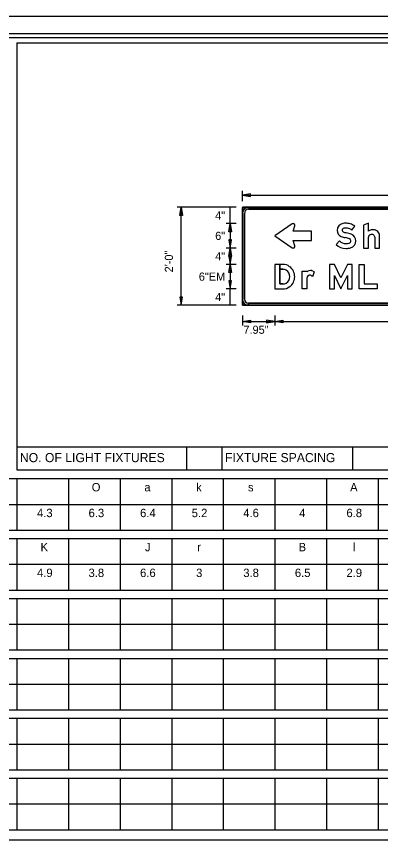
# Model space of a CAD drawing. Extents: x 1374 to 1480, y 568 to 638.
# Drawn here: x 1410.25 to 1417.68, y 587.74 to 604.64 of the extents above; entities that cross this region are included whole.
import ezdxf

# ---------------------------------------------------------------- set-up
doc = ezdxf.new("R2010")
doc.units = 0
for name, color, linetype in [('GSBWFill', 7, 'Continuous'), ('GSColorFill', 7, 'Continuous'), ('GSDims', 7, 'Continuous'), ('GSOutline', 7, 'Continuous'), ('GSSign', 7, 'Continuous'), ('PlotBorder_dp', 7, 'Continuous'), ('SheetBorder_dp', 7, 'Continuous'), ('SheetLinesMisc2_dp', 7, 'Continuous'), ('TextMinor', 7, 'Continuous')]:
    doc.layers.add(name, color=color, linetype=linetype)

msp = doc.modelspace()

# ---------------------------------------------------------------- linework, layer by layer
at = {"layer": 'GSBWFill'}
for p, q in [((1423.858, 600.75), (1414.858, 600.75)), ((1414.858, 600.75), (1414.858, 598.75)), ((1423.733, 600.75), (1414.983, 600.75)), ((1414.983, 600.708), (1423.733, 600.708)), ((1414.858, 600.625), (1414.858, 598.875)), ((1414.9, 598.875), (1414.9, 600.625)), ((1416.326, 599.432), (1416.292, 599.33)), ((1415.684, 599.183), (1415.62, 599.183)), ((1414.858, 598.75), (1423.858, 598.75)), ((1414.983, 598.75), (1414.983, 598.791)), ((1423.733, 598.791), (1414.984, 598.791)), ((1414.984, 598.791), (1414.984, 598.75)), ((1414.984, 598.75), (1423.733, 598.75))]:
    msp.add_line(p, q, dxfattribs=at)
for points in [[(1415.877, 600.41), (1415.521, 600.166), (1415.877, 599.923)], [(1416.271, 600.073), (1416.271, 600.259), (1415.897, 600.259), (1415.931, 600.37)], [(1417.091, 600.284), (1417.152, 600.363)], [(1417.431, 600.263), (1417.431, 600.425), (1417.331, 600.386), (1417.331, 599.916), (1417.431, 599.916), (1417.431, 600.136)], [(1417.561, 600.136), (1417.561, 599.916), (1417.661, 599.916), (1417.661, 600.168)], [(1415.931, 599.963), (1415.897, 600.073), (1416.271, 600.073)], [(1416.841, 600.063), (1416.771, 599.992)], [(1415.62, 599.183), (1415.62, 599.583), (1415.521, 599.583), (1415.521, 599.083), (1415.684, 599.083)], [(1415.684, 599.583), (1415.62, 599.583), (1415.62, 599.483), (1415.684, 599.483)], [(1416.176, 599.285), (1416.176, 599.083), (1416.076, 599.083), (1416.076, 599.448), (1416.176, 599.448), (1416.176, 599.432)]]:
    msp.add_lwpolyline(points, dxfattribs=at)
for points in [[(1417.003, 599.355), (1417.003, 599.083), (1417.103, 599.083), (1417.103, 599.583), (1417.003, 599.583), (1416.871, 599.311), (1416.738, 599.583), (1416.638, 599.583), (1416.638, 599.083), (1416.738, 599.083), (1416.738, 599.355), (1416.871, 599.083)], [(1417.343, 599.183), (1417.613, 599.183), (1417.613, 599.083), (1417.243, 599.083), (1417.243, 599.583), (1417.343, 599.583)]]:
    msp.add_lwpolyline(points, close=True, dxfattribs=at)
for centre, radius, start, end in [((1414.983, 600.625), 0.125, 90, 180), ((1414.983, 600.625), 0.0833, 90, 180), ((1415.897, 600.38), 0.0361, 342.9427, 124.3997), ((1416.938, 600.278), 0.143, 101.6172, 180), ((1416.968, 600.13), 0.295, 90, 101.6172), ((1416.968, 600.063), 0.361, 75.2778, 90), ((1417.002, 600.19), 0.229, 48.8597, 75.2778), ((1416.927, 600.278), 0.133, 180, 248.2079), ((1416.938, 600.278), 0.0432, 101.6172, 180), ((1416.927, 600.278), 0.0327, 180, 248.2079), ((1417.036, 600.55), 0.326, 248.2079, 259.4488), ((1416.968, 600.13), 0.195, 90, 101.6172), ((1416.968, 600.063), 0.261, 75.2778, 90), ((1416.865, 599.631), 0.609, 69.1129, 79.4488), ((1417.002, 600.19), 0.129, 46.4926, 75.2778), ((1417.03, 600.064), 0.146, 0, 69.1129), ((1417.527, 600.111), 0.18, 103.4695, 122.4943), ((1417.491, 600.132), 0.0609, 131.0076, 154.5283), ((1417.496, 600.126), 0.0688, 109.8074, 131.0076), ((1417.499, 600.116), 0.0787, 90, 109.8074), ((1417.529, 600.091), 0.2, 90, 102.6043), ((1417.499, 600.132), 0.0632, 68.0808, 90), ((1417.5, 600.134), 0.0613, 45.8298, 68.0808), ((1417.529, 600.15), 0.141, 68.8636, 90), ((1417.501, 600.135), 0.0598, 23.0928, 45.8298), ((1417.532, 600.159), 0.131, 46.975, 68.8636), ((1417.538, 600.165), 0.124, 23.9317, 46.975), ((1417.546, 600.168), 0.115, 0, 23.9317), ((1416.974, 600.198), 0.189, 225.2528, 270), ((1417.036, 600.55), 0.426, 248.2079, 259.4488), ((1416.865, 599.631), 0.509, 69.1129, 79.4488), ((1416.974, 600.263), 0.254, 270, 284.8926), ((1417.027, 600.064), 0.0485, 284.8926, 360), ((1417.03, 600.064), 0.0457, 360, 69.1129), ((1417.027, 600.064), 0.149, 284.8926, 360), ((1417.483, 600.136), 0.0521, 154.5283, 180), ((1417.503, 600.136), 0.058, 0, 23.0928), ((1415.897, 599.952), 0.0361, 235.6003, 17.0573), ((1416.974, 600.198), 0.289, 225.2528, 270), ((1416.974, 600.263), 0.354, 270, 284.8926), ((1414.983, 598.875), 0.125, 180, 270), ((1414.983, 598.875), 0.0833, 180, 270)]:
    msp.add_arc(centre, radius, start, end, dxfattribs=at)
for centre, major_axis, ratio, start_param, end_param in [((1415.69, 599.364), (0, 0.219), 0.992009, 5.621793, 6.313477), ((1415.679, 599.335), (0, 0.249), 0.992009, 4.702399, 5.655315), ((1415.686, 599.348), (0, 0.135), 0.992009, 5.75224, 6.301036), ((1415.677, 599.337), (0, 0.149), 0.992009, 4.686283, 5.735161), ((1415.677, 599.329), (0, 0.149), 0.992009, 3.689617, 4.738495), ((1415.679, 599.33), (0, 0.249), 0.992009, 3.769463, 4.722379), ((1416.276, 599.298), (0, 0.167), 0.99999, 0.443663, 0.646229), ((1416.255, 599.301), (0, 0.0781), 0.99999, 1.188904, 1.450084), ((1416.229, 599.312), (0, 0.05), 0.99999, 0.293855, 1.188904), ((1416.237, 599.381), (0, 0.075), 0.99999, 0.24142, 0.443663), ((1416.23, 599.309), (0, 0.0534), 0.99999, 0.067293, 0.293855), ((1416.25, 599.329), (0, 0.129), 0.99999, 6.103268, 6.524606), ((1416.231, 599.282), (0, 0.08), 0.99999, 6.094384, 6.350479), ((1416.234, 599.293), (0, 0.0688), 0.99999, 5.27661, 6.094384), ((1416.252, 599.345), (0, 0.112), 0.99999, 5.846069, 6.103268), ((1416.241, 599.321), (0, 0.14), 0.99999, 5.631644, 5.846069), ((1415.686, 599.318), (0, 0.135), 0.992009, 3.123742, 3.672538), ((1416.388, 599.284), (0, 0.212), 0.99999, 1.445958, 1.569673), ((1415.69, 599.302), (0, 0.219), 0.992009, 3.111301, 3.802985)]:
    msp.add_ellipse(centre, major_axis=major_axis, ratio=ratio, start_param=start_param, end_param=end_param, dxfattribs=at)
at = {"layer": 'GSColorFill'}
for p, q in [((1423.858, 600.75), (1414.858, 600.75)), ((1414.858, 600.75), (1414.858, 598.75)), ((1423.858, 600.75), (1414.858, 600.75)), ((1414.858, 600.75), (1414.858, 598.754)), ((1414.862, 598.754), (1414.862, 600.745)), ((1414.862, 600.745), (1423.854, 600.745)), ((1423.733, 600.75), (1414.983, 600.75)), ((1414.983, 600.708), (1423.733, 600.708)), ((1414.858, 600.625), (1414.858, 598.875)), ((1414.9, 598.875), (1414.9, 600.625)), ((1416.326, 599.432), (1416.292, 599.33)), ((1415.684, 599.183), (1415.62, 599.183)), ((1414.858, 598.754), (1414.862, 598.754)), ((1423.854, 598.754), (1414.858, 598.754)), ((1414.858, 598.754), (1414.858, 598.75)), ((1414.858, 598.75), (1423.858, 598.75)), ((1414.858, 598.75), (1423.858, 598.75)), ((1414.983, 598.75), (1414.983, 598.791)), ((1423.733, 598.791), (1414.984, 598.791)), ((1414.984, 598.791), (1414.984, 598.75)), ((1414.984, 598.75), (1423.733, 598.75))]:
    msp.add_line(p, q, dxfattribs=at)
for points in [[(1415.877, 600.41), (1415.521, 600.166), (1415.877, 599.923)], [(1416.271, 600.073), (1416.271, 600.259), (1415.897, 600.259), (1415.931, 600.37)], [(1417.091, 600.284), (1417.152, 600.363)], [(1417.431, 600.263), (1417.431, 600.425), (1417.331, 600.386), (1417.331, 599.916), (1417.431, 599.916), (1417.431, 600.136)], [(1417.561, 600.136), (1417.561, 599.916), (1417.661, 599.916), (1417.661, 600.168)], [(1415.931, 599.963), (1415.897, 600.073), (1416.271, 600.073)], [(1416.841, 600.063), (1416.771, 599.992)], [(1415.62, 599.183), (1415.62, 599.583), (1415.521, 599.583), (1415.521, 599.083), (1415.684, 599.083)], [(1415.684, 599.583), (1415.62, 599.583), (1415.62, 599.483), (1415.684, 599.483)], [(1416.176, 599.285), (1416.176, 599.083), (1416.076, 599.083), (1416.076, 599.448), (1416.176, 599.448), (1416.176, 599.432)]]:
    msp.add_lwpolyline(points, dxfattribs=at)
for points in [[(1417.003, 599.355), (1417.003, 599.083), (1417.103, 599.083), (1417.103, 599.583), (1417.003, 599.583), (1416.871, 599.311), (1416.738, 599.583), (1416.638, 599.583), (1416.638, 599.083), (1416.738, 599.083), (1416.738, 599.355), (1416.871, 599.083)], [(1417.343, 599.183), (1417.613, 599.183), (1417.613, 599.083), (1417.243, 599.083), (1417.243, 599.583), (1417.343, 599.583)]]:
    msp.add_lwpolyline(points, close=True, dxfattribs=at)
for centre, radius, start, end in [((1414.983, 600.625), 0.125, 90, 180), ((1414.983, 600.625), 0.0833, 90, 180), ((1415.897, 600.38), 0.0361, 342.9427, 124.3997), ((1416.938, 600.278), 0.143, 101.6172, 180), ((1416.968, 600.13), 0.295, 90, 101.6172), ((1416.968, 600.063), 0.361, 75.2778, 90), ((1417.002, 600.19), 0.229, 48.8597, 75.2778), ((1416.927, 600.278), 0.133, 180, 248.2079), ((1416.938, 600.278), 0.0432, 101.6172, 180), ((1416.927, 600.278), 0.0327, 180, 248.2079), ((1417.036, 600.55), 0.326, 248.2079, 259.4488), ((1416.968, 600.13), 0.195, 90, 101.6172), ((1416.968, 600.063), 0.261, 75.2778, 90), ((1416.865, 599.631), 0.609, 69.1129, 79.4488), ((1417.002, 600.19), 0.129, 46.4926, 75.2778), ((1417.03, 600.064), 0.146, 0, 69.1129), ((1417.527, 600.111), 0.18, 103.4695, 122.4943), ((1417.491, 600.132), 0.0609, 131.0076, 154.5283), ((1417.496, 600.126), 0.0688, 109.8074, 131.0076), ((1417.499, 600.116), 0.0787, 90, 109.8074), ((1417.529, 600.091), 0.2, 90, 102.6043), ((1417.499, 600.132), 0.0632, 68.0808, 90), ((1417.5, 600.134), 0.0613, 45.8298, 68.0808), ((1417.529, 600.15), 0.141, 68.8636, 90), ((1417.501, 600.135), 0.0598, 23.0928, 45.8298), ((1417.532, 600.159), 0.131, 46.975, 68.8636), ((1417.538, 600.165), 0.124, 23.9317, 46.975), ((1417.546, 600.168), 0.115, 0, 23.9317), ((1416.974, 600.198), 0.189, 225.2528, 270), ((1417.036, 600.55), 0.426, 248.2079, 259.4488), ((1416.865, 599.631), 0.509, 69.1129, 79.4488), ((1416.974, 600.263), 0.254, 270, 284.8926), ((1417.027, 600.064), 0.0485, 284.8926, 360), ((1417.03, 600.064), 0.0457, 360, 69.1129), ((1417.027, 600.064), 0.149, 284.8926, 360), ((1417.483, 600.136), 0.0521, 154.5283, 180), ((1417.503, 600.136), 0.058, 0, 23.0928), ((1415.897, 599.952), 0.0361, 235.6003, 17.0573), ((1416.974, 600.198), 0.289, 225.2528, 270), ((1416.974, 600.263), 0.354, 270, 284.8926), ((1414.983, 598.875), 0.125, 180, 270), ((1414.983, 598.875), 0.0833, 180, 270)]:
    msp.add_arc(centre, radius, start, end, dxfattribs=at)
for centre, major_axis, ratio, start_param, end_param in [((1415.69, 599.364), (0, 0.219), 0.992009, 5.621793, 6.313477), ((1415.679, 599.335), (0, 0.249), 0.992009, 4.702399, 5.655315), ((1415.686, 599.348), (0, 0.135), 0.992009, 5.75224, 6.301036), ((1415.677, 599.337), (0, 0.149), 0.992009, 4.686283, 5.735161), ((1415.677, 599.329), (0, 0.149), 0.992009, 3.689617, 4.738495), ((1415.679, 599.33), (0, 0.249), 0.992009, 3.769463, 4.722379), ((1416.276, 599.298), (0, 0.167), 0.99999, 0.443663, 0.646229), ((1416.255, 599.301), (0, 0.0781), 0.99999, 1.188904, 1.450084), ((1416.229, 599.312), (0, 0.05), 0.99999, 0.293855, 1.188904), ((1416.237, 599.381), (0, 0.075), 0.99999, 0.24142, 0.443663), ((1416.23, 599.309), (0, 0.0534), 0.99999, 0.067293, 0.293855), ((1416.25, 599.329), (0, 0.129), 0.99999, 6.103268, 6.524606), ((1416.231, 599.282), (0, 0.08), 0.99999, 6.094384, 6.350479), ((1416.234, 599.293), (0, 0.0688), 0.99999, 5.27661, 6.094384), ((1416.252, 599.345), (0, 0.112), 0.99999, 5.846069, 6.103268), ((1416.241, 599.321), (0, 0.14), 0.99999, 5.631644, 5.846069), ((1415.686, 599.318), (0, 0.135), 0.992009, 3.123742, 3.672538), ((1416.388, 599.284), (0, 0.212), 0.99999, 1.445958, 1.569673), ((1415.69, 599.302), (0, 0.219), 0.992009, 3.111301, 3.802985)]:
    msp.add_ellipse(centre, major_axis=major_axis, ratio=ratio, start_param=start_param, end_param=end_param, dxfattribs=at)
at = {"layer": 'GSDims'}
for p, q in [((1414.858, 600.875), (1414.858, 601.083)), ((1414.858, 601), (1423.858, 601)), ((1414.858, 600.875), (1414.858, 600.875)), ((1413.733, 600.75), (1413.525, 600.75)), ((1413.608, 598.75), (1413.608, 600.75)), ((1414.733, 600.75), (1413.733, 600.75)), ((1414.733, 600.75), (1414.525, 600.75)), ((1414.608, 600.416), (1414.608, 600.75)), ((1414.733, 600.416), (1414.525, 600.416)), ((1414.733, 600.416), (1414.525, 600.416)), ((1414.608, 600.416), (1414.608, 599.916)), ((1414.733, 599.916), (1414.525, 599.916)), ((1414.733, 599.916), (1414.525, 599.916)), ((1414.608, 599.583), (1414.608, 599.916)), ((1414.733, 599.583), (1414.525, 599.583)), ((1414.733, 599.583), (1414.525, 599.583)), ((1414.608, 599.583), (1414.608, 599.083)), ((1414.733, 599.083), (1414.525, 599.083)), ((1414.733, 599.083), (1414.525, 599.083)), ((1414.608, 598.75), (1414.608, 599.083)), ((1413.733, 598.75), (1413.525, 598.75)), ((1414.733, 598.75), (1413.733, 598.75)), ((1414.733, 598.75), (1414.525, 598.75)), ((1414.858, 598.541), (1414.858, 598.333)), ((1414.858, 598.541), (1414.858, 598.333)), ((1415.521, 598.541), (1415.521, 598.333)), ((1415.521, 598.541), (1415.521, 598.333)), ((1414.858, 598.416), (1415.521, 598.416)), ((1415.521, 598.416), (1423.196, 598.416))]:
    msp.add_line(p, q, dxfattribs=at)
for points in [[(1414.858, 601), (1415.025, 600.972), (1415.025, 601.027)], [(1413.608, 600.75), (1413.636, 600.583), (1413.58, 600.583)], [(1414.608, 600.416), (1414.636, 600.25), (1414.58, 600.25)], [(1414.608, 599.916), (1414.636, 600.083), (1414.58, 600.083)], [(1414.608, 599.916), (1414.636, 599.75), (1414.58, 599.75)], [(1414.608, 599.583), (1414.636, 599.75), (1414.58, 599.75)], [(1414.608, 599.583), (1414.636, 599.416), (1414.58, 599.416)], [(1414.608, 599.083), (1414.636, 599.25), (1414.58, 599.25)], [(1413.608, 598.75), (1413.636, 598.916), (1413.58, 598.916)], [(1414.858, 598.416), (1415.025, 598.444), (1415.025, 598.388)], [(1415.521, 598.416), (1415.354, 598.444), (1415.354, 598.388)], [(1415.521, 598.416), (1415.687, 598.444), (1415.687, 598.388)]]:
    msp.add_lwpolyline(points, close=True, dxfattribs=at)
at = {"layer": 'GSOutline'}
for p, q in [((1423.858, 600.75), (1414.858, 600.75)), ((1414.858, 600.75), (1414.858, 598.75)), ((1423.733, 600.75), (1414.983, 600.75)), ((1423.733, 600.708), (1414.983, 600.708)), ((1414.858, 600.625), (1414.858, 598.875)), ((1414.9, 600.625), (1414.9, 598.875)), ((1416.326, 599.432), (1416.292, 599.33)), ((1415.684, 599.183), (1415.684, 599.183)), ((1415.684, 599.083), (1415.684, 599.083)), ((1414.858, 598.75), (1423.858, 598.75)), ((1414.983, 598.791), (1423.733, 598.791)), ((1414.983, 598.75), (1423.733, 598.75))]:
    msp.add_line(p, q, dxfattribs=at)
for points in [[(1415.877, 600.41), (1415.521, 600.166), (1415.877, 599.923)], [(1416.271, 600.073), (1416.271, 600.259), (1415.897, 600.259), (1415.931, 600.37)], [(1417.091, 600.284), (1417.152, 600.363)], [(1417.431, 600.263), (1417.431, 600.425), (1417.331, 600.386), (1417.331, 599.916), (1417.431, 599.916), (1417.431, 600.136)], [(1417.561, 600.136), (1417.561, 599.916), (1417.661, 599.916), (1417.661, 600.168)], [(1415.931, 599.963), (1415.897, 600.073), (1416.271, 600.073)], [(1416.841, 600.063), (1416.771, 599.992)], [(1415.684, 599.583), (1415.521, 599.583), (1415.521, 599.083), (1415.684, 599.083)], [(1415.684, 599.483), (1415.62, 599.483), (1415.62, 599.183), (1415.684, 599.183)], [(1416.176, 599.285), (1416.176, 599.083), (1416.076, 599.083), (1416.076, 599.448), (1416.176, 599.448), (1416.176, 599.432)]]:
    msp.add_lwpolyline(points, dxfattribs=at)
for points in [[(1417.003, 599.355), (1417.003, 599.083), (1417.103, 599.083), (1417.103, 599.583), (1417.003, 599.583), (1416.871, 599.311), (1416.738, 599.583), (1416.638, 599.583), (1416.638, 599.083), (1416.738, 599.083), (1416.738, 599.355), (1416.871, 599.083)], [(1417.343, 599.183), (1417.613, 599.183), (1417.613, 599.083), (1417.243, 599.083), (1417.243, 599.583), (1417.343, 599.583)]]:
    msp.add_lwpolyline(points, close=True, dxfattribs=at)
for centre, radius, start, end in [((1414.983, 600.625), 0.125, 90, 180), ((1414.983, 600.625), 0.0833, 90, 180), ((1415.897, 600.38), 0.0361, 342.9427, 124.3997), ((1416.938, 600.278), 0.143, 101.6172, 180), ((1416.968, 600.13), 0.295, 90, 101.6172), ((1416.968, 600.063), 0.361, 75.2778, 90), ((1417.002, 600.19), 0.229, 48.8597, 75.2778), ((1416.927, 600.278), 0.133, 180, 248.2079), ((1416.938, 600.278), 0.0432, 101.6172, 180), ((1416.927, 600.278), 0.0327, 180, 248.2079), ((1417.036, 600.55), 0.326, 248.2079, 259.4488), ((1416.968, 600.13), 0.195, 90, 101.6172), ((1416.968, 600.063), 0.261, 75.2778, 90), ((1416.865, 599.631), 0.609, 69.1129, 79.4488), ((1417.002, 600.19), 0.129, 46.4926, 75.2778), ((1417.03, 600.064), 0.146, 0, 69.1129), ((1417.527, 600.111), 0.18, 103.4695, 122.4943), ((1417.491, 600.132), 0.0609, 131.0076, 154.5283), ((1417.496, 600.126), 0.0688, 109.8074, 131.0076), ((1417.499, 600.116), 0.0787, 90, 109.8074), ((1417.529, 600.091), 0.2, 90, 102.6043), ((1417.499, 600.132), 0.0632, 68.0808, 90), ((1417.5, 600.134), 0.0613, 45.8298, 68.0808), ((1417.529, 600.15), 0.141, 68.8636, 90), ((1417.501, 600.135), 0.0598, 23.0928, 45.8298), ((1417.532, 600.159), 0.131, 46.975, 68.8636), ((1417.538, 600.165), 0.124, 23.9317, 46.975), ((1417.546, 600.168), 0.115, 0, 23.9317), ((1416.974, 600.198), 0.189, 225.2528, 270), ((1417.036, 600.55), 0.426, 248.2079, 259.4488), ((1416.865, 599.631), 0.509, 69.1129, 79.4488), ((1416.974, 600.263), 0.254, 270, 284.8926), ((1417.027, 600.064), 0.0485, 284.8926, 360), ((1417.03, 600.064), 0.0457, 360, 69.1129), ((1417.027, 600.064), 0.149, 284.8926, 360), ((1417.483, 600.136), 0.0521, 154.5283, 180), ((1417.503, 600.136), 0.058, 0, 23.0928), ((1415.897, 599.952), 0.0361, 235.6003, 17.0573), ((1416.974, 600.198), 0.289, 225.2528, 270), ((1416.974, 600.263), 0.354, 270, 284.8926), ((1414.983, 598.875), 0.125, 180, 270), ((1414.983, 598.875), 0.0833, 180, 270)]:
    msp.add_arc(centre, radius, start, end, dxfattribs=at)
for centre, major_axis, ratio, start_param, end_param in [((1415.69, 599.364), (0, 0.219), 0.992009, 5.621793, 6.313477), ((1415.679, 599.335), (0, 0.249), 0.992009, 4.702399, 5.655315), ((1415.686, 599.348), (0, 0.135), 0.992009, 5.75224, 6.301036), ((1415.677, 599.337), (0, 0.149), 0.992009, 4.686283, 5.735161), ((1415.677, 599.329), (0, 0.149), 0.992009, 3.689617, 4.738495), ((1415.679, 599.33), (0, 0.249), 0.992009, 3.769463, 4.722379), ((1416.276, 599.298), (0, 0.167), 0.99999, 0.443663, 0.646229), ((1416.255, 599.301), (0, 0.0781), 0.99999, 1.188904, 1.450084), ((1416.229, 599.312), (0, 0.05), 0.99999, 0.293855, 1.188904), ((1416.237, 599.381), (0, 0.075), 0.99999, 0.24142, 0.443663), ((1416.23, 599.309), (0, 0.0534), 0.99999, 0.067293, 0.293855), ((1416.25, 599.329), (0, 0.129), 0.99999, 6.103268, 6.524606), ((1416.231, 599.282), (0, 0.08), 0.99999, 6.094384, 6.350479), ((1416.234, 599.293), (0, 0.0688), 0.99999, 5.27661, 6.094384), ((1416.252, 599.345), (0, 0.113), 0.99999, 5.846069, 6.103268), ((1416.241, 599.321), (0, 0.14), 0.99999, 5.631644, 5.846069), ((1415.686, 599.318), (0, 0.135), 0.992009, 3.123742, 3.672538), ((1416.388, 599.284), (0, 0.212), 0.99999, 1.445958, 1.569673), ((1415.69, 599.302), (0, 0.219), 0.992009, 3.111301, 3.802985)]:
    msp.add_ellipse(centre, major_axis=major_axis, ratio=ratio, start_param=start_param, end_param=end_param, dxfattribs=at)
at = {"layer": 'PlotBorder_dp'}
msp.add_lwpolyline([(1400.035, 568.275), (1456.648, 568.275), (1456.648, 604.644), (1400.035, 604.644)], close=True, dxfattribs=at)
at = {"layer": 'SheetBorder_dp'}
msp.add_line((1401.922, 604.301), (1454.76, 604.301), dxfattribs=at)
at = {"layer": 'SheetLinesMisc2_dp'}
for p, q in [((1402.016, 604.22), (1454.669, 604.22)), ((1410.256, 604.111), (1428.163, 604.111)), ((1410.256, 604.111), (1410.256, 595.388)), ((1410.256, 595.855), (1428.163, 595.855)), ((1413.715, 595.855), (1413.715, 595.388)), ((1414.439, 595.855), (1414.439, 595.388)), ((1417.106, 595.855), (1417.106, 595.388)), ((1410.256, 595.388), (1428.163, 595.388)), ((1402.268, 595.208), (1428.163, 595.208)), ((1410.256, 595.208), (1410.256, 594.156)), ((1411.309, 595.208), (1411.309, 594.156)), ((1412.362, 595.208), (1412.362, 594.156)), ((1413.415, 595.208), (1413.415, 594.156)), ((1414.469, 595.208), (1414.469, 594.156)), ((1415.522, 595.208), (1415.522, 594.156)), ((1416.576, 595.208), (1416.576, 594.156)), ((1417.629, 595.208), (1417.629, 594.156)), ((1402.268, 594.682), (1428.163, 594.682)), ((1402.268, 594.156), (1428.163, 594.156)), ((1402.268, 593.985), (1428.163, 593.985)), ((1410.256, 593.985), (1410.256, 592.933)), ((1411.309, 593.985), (1411.309, 592.933)), ((1412.362, 593.985), (1412.362, 592.933)), ((1413.415, 593.985), (1413.415, 592.933)), ((1414.469, 593.985), (1414.469, 592.933)), ((1415.522, 593.985), (1415.522, 592.933)), ((1416.576, 593.985), (1416.576, 592.933)), ((1417.629, 593.985), (1417.629, 592.933)), ((1402.268, 593.459), (1428.163, 593.459)), ((1402.268, 592.933), (1428.163, 592.933)), ((1402.268, 592.761), (1428.163, 592.761)), ((1410.256, 592.761), (1410.256, 591.709)), ((1411.309, 592.761), (1411.309, 591.709)), ((1412.362, 592.761), (1412.362, 591.709)), ((1413.415, 592.761), (1413.415, 591.709)), ((1414.469, 592.761), (1414.469, 591.709)), ((1415.522, 592.761), (1415.522, 591.709)), ((1416.576, 592.761), (1416.576, 591.709)), ((1417.629, 592.761), (1417.629, 591.709)), ((1402.268, 592.235), (1428.163, 592.235)), ((1402.268, 591.709), (1428.163, 591.709)), ((1402.268, 591.538), (1428.163, 591.538)), ((1410.256, 591.538), (1410.256, 590.486)), ((1411.309, 591.538), (1411.309, 590.486)), ((1412.362, 591.538), (1412.362, 590.486)), ((1413.415, 591.538), (1413.415, 590.486)), ((1414.469, 591.538), (1414.469, 590.486)), ((1415.522, 591.538), (1415.522, 590.486)), ((1416.576, 591.538), (1416.576, 590.486)), ((1417.629, 591.538), (1417.629, 590.486)), ((1402.268, 591.012), (1428.163, 591.012)), ((1402.268, 590.486), (1428.163, 590.486)), ((1402.268, 590.314), (1428.163, 590.314)), ((1410.256, 590.314), (1410.256, 589.262)), ((1411.309, 590.314), (1411.309, 589.262)), ((1412.362, 590.314), (1412.362, 589.262)), ((1413.415, 590.314), (1413.415, 589.262)), ((1414.469, 590.314), (1414.469, 589.262)), ((1415.522, 590.314), (1415.522, 589.262)), ((1416.576, 590.314), (1416.576, 589.262)), ((1417.629, 590.314), (1417.629, 589.262)), ((1402.268, 589.788), (1428.163, 589.788)), ((1402.268, 589.262), (1428.163, 589.262)), ((1402.268, 589.09), (1428.163, 589.09)), ((1410.256, 589.09), (1410.256, 588.039)), ((1411.309, 589.09), (1411.309, 588.039)), ((1412.362, 589.09), (1412.362, 588.039)), ((1413.415, 589.09), (1413.415, 588.039)), ((1414.469, 589.09), (1414.469, 588.039)), ((1415.522, 589.09), (1415.522, 588.039)), ((1416.576, 589.09), (1416.576, 588.039)), ((1417.629, 589.09), (1417.629, 588.039)), ((1402.268, 588.565), (1428.163, 588.565)), ((1402.268, 588.039), (1428.163, 588.039)), ((1402.016, 587.832), (1454.669, 587.832))]:
    msp.add_line(p, q, dxfattribs=at)

# ---------------------------------------------------------------- texts
at = {"layer": 'GSDims'}
for s, p in [('4"', (1414.303, 600.5)), ('6"', (1414.303, 600.083)), ('4"', (1414.303, 599.666)), ('6"EM', (1413.969, 599.25)), ('4"', (1414.303, 598.833)), ('7.95"', (1414.88, 598.166))]:
    msp.add_text(s, height=0.1667, dxfattribs=at).set_placement(p)
msp.add_text('2\'-0"', height=0.1667, rotation=90, dxfattribs=at).set_placement((1413.441, 599.42))
at = {"layer": 'GSSign'}
for s, height, p in [('O', 0.171, (1411.783, 594.948)), ('k', 0.171, (1413.914, 594.948)), ('A', 0.171, (1417.058, 594.948)), ('a', 0.171, (1412.857, 594.948)), ('s', 0.171, (1414.972, 594.948)), ('4.3', 0.1715, (1410.665, 594.422)), ('6.3', 0.1715, (1411.718, 594.422)), ('6.4', 0.1715, (1412.77, 594.422)), ('5.2', 0.1715, (1413.824, 594.422)), ('4.6', 0.1715, (1414.876, 594.422)), ('4', 0.171, (1416.019, 594.422)), ('6.8', 0.1715, (1416.983, 594.422)), ('K', 0.171, (1410.738, 593.725)), ('J', 0.171, (1412.87, 593.725)), ('r', 0.171, (1413.936, 593.725)), ('B', 0.171, (1416.007, 593.725)), ('l', 0.171, (1417.113, 593.725)), ('4.9', 0.1715, (1410.665, 593.199)), ('3.8', 0.1715, (1411.717, 593.199)), ('6.6', 0.1715, (1412.77, 593.199)), ('3', 0.171, (1413.914, 593.199)), ('3.8', 0.1715, (1414.877, 593.199)), ('6.5', 0.1715, (1415.93, 593.199)), ('2.9', 0.1715, (1416.983, 593.199))]:
    msp.add_text(s, height=height, dxfattribs=at).set_placement(p)
at = {"layer": 'TextMinor'}
for s, p in [('NO. OF LIGHT FIXTURES', (1410.316, 595.545)), ('FIXTURE SPACING', (1414.504, 595.545))]:
    msp.add_text(s, height=0.18601, dxfattribs=at).set_placement(p)

doc.saveas('drawing.dxf')
